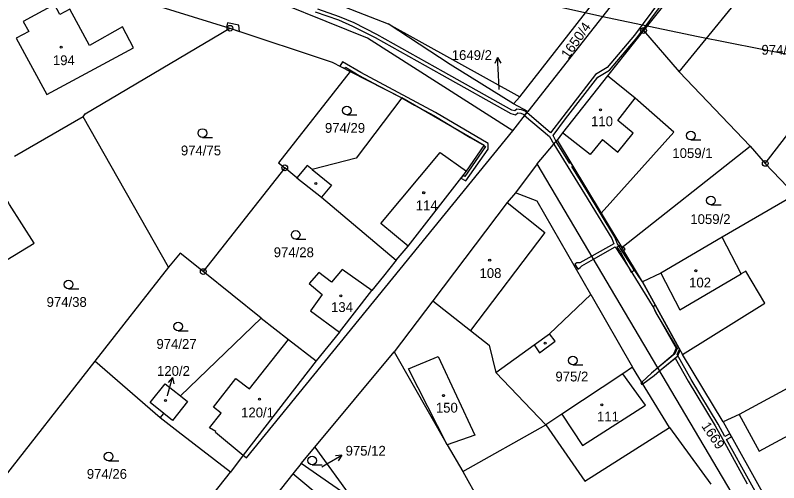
# Model space of a CAD drawing. Extents: x -680203 to -673936, y -1102717 to -1093650.
# Drawn here: x -676795.2 to -676663.1, y -1100739.7 to -1100658.8 of the extents above; entities that cross this region are included whole.
import ezdxf

# ---------------------------------------------------------------- set-up
doc = ezdxf.new("R2010")
doc.units = 0
for name, color, linetype in [('_Ideová část', 7, 'Continuous'), ('SOxx02xx_Koleje_param další_Popis10', 7, 'Continuous'), ('SOxx02xx_Staničení_Popis10', 7, 'Continuous'), ('SOxxxxxx_Koleje_hlavní_body_Popis10', 7, 'Continuous'), ('SOxxxxxx_Koleje_LN_parametry_Popis10', 7, 'Continuous'), ('SOxxxxxx_Koleje_param další_Popis10', 7, 'Continuous'), ('SOxxxxxx_Osa_bod_P', 7, 'Continuous'), ('SOxxxxxx_Staničení_Popis10', 7, 'Continuous'), ('x_prac', 7, 'Continuous')]:
    doc.layers.add(name, color=color, linetype=linetype)

msp = doc.modelspace()

# ---------------------------------------------------------------- linework, layer by layer
at = {"layer": '_Ideová část'}
msp.add_circle((-676417.7, -1099401.52), 1287.12, dxfattribs=at)
at = {"layer": 'SOxx02xx_Koleje_param další_Popis10'}
for centre, radius in [((-676758.11, -1100661.01), 0.5), ((-676758.11, -1100661.01), 0.0303), ((-676686.55, -1100661.4), 0.5), ((-676686.55, -1100661.4), 0.0303), ((-676665.48, -1100684.42), 0.5), ((-676665.48, -1100684.42), 0.0303), ((-676748.62, -1100685.19), 0.5), ((-676748.62, -1100685.19), 0.0303), ((-676762.71, -1100703.16), 0.5), ((-676762.71, -1100703.16), 0.0303)]:
    msp.add_circle(centre, radius, dxfattribs=at)
at = {"layer": 'SOxx02xx_Staničení_Popis10'}
for p, q in [((-676711.8, -1100666.08), (-676712.24, -1100667.11)), ((-676711.64, -1100669.08), (-676711.8, -1100666.08)), ((-676711.8, -1100666.08), (-676711.24, -1100667.06)), ((-676711.51, -1100671.62), (-676711.64, -1100669.08)), ((-676768.84, -1100724.41), (-676768.06, -1100721.51)), ((-676768.06, -1100721.51), (-676768.81, -1100722.35)), ((-676768.06, -1100721.51), (-676767.84, -1100722.61)), ((-676768.91, -1100724.66), (-676768.84, -1100724.41)), ((-676741.34, -1100736.48), (-676738.74, -1100734.98)), ((-676738.74, -1100734.98), (-676739.86, -1100735.05)), ((-676738.74, -1100734.98), (-676739.36, -1100735.91)), ((-676742.18, -1100736.97), (-676741.34, -1100736.48))]:
    msp.add_line(p, q, dxfattribs=at)
at = {"layer": 'SOxxxxxx_Koleje_hlavní_body_Popis10'}
for p, q in [((-676737.89, -1100676), (-676736.14, -1100676)), ((-676762.87, -1100679.91), (-676761.12, -1100679.91)), ((-676678.35, -1100680.36), (-676676.6, -1100680.36)), ((-676674.87, -1100691.58), (-676673.12, -1100691.58)), ((-676746.73, -1100697.53), (-676744.98, -1100697.53)), ((-676786.02, -1100706.14), (-676784.27, -1100706.14)), ((-676767.08, -1100713.42), (-676765.33, -1100713.42)), ((-676698.77, -1100719.32), (-676697.02, -1100719.32)), ((-676779.09, -1100735.93), (-676777.34, -1100735.93)), ((-676743.87, -1100736.61), (-676742.12, -1100736.61))]:
    msp.add_line(p, q, dxfattribs=at)
for centre in [(-676737.89, -1100675.25), (-676762.87, -1100679.16), (-676678.35, -1100679.61), (-676674.87, -1100690.83), (-676746.73, -1100696.78), (-676786.02, -1100705.39), (-676767.08, -1100712.67), (-676698.77, -1100718.57), (-676779.09, -1100735.18), (-676743.87, -1100735.86)]:
    msp.add_circle(centre, 0.75, dxfattribs=at)
at = {"layer": 'SOxxxxxx_Koleje_LN_parametry_Popis10'}
for points in [[(-676662.09, -1100628.29), (-676666.67, -1100634.24), (-676670.09, -1100639.09), (-676677.03, -1100647.89), (-676683.58, -1100656.15), (-676688.08, -1100662.21), (-676692.84, -1100667.81), (-676694.86, -1100669), (-676700.53, -1100676.36), (-676702.61, -1100679.14), (-676706.75, -1100675.62), (-676707.12, -1100676.1), (-676702.8, -1100679.76), (-676702.06, -1100681.09), (-676696.73, -1100689.68), (-676692.05, -1100697.44), (-676691.7, -1100698.34), (-676695.5, -1100700.49), (-676697.54, -1100701.64)], [(-676666.3, -1100742.87), (-676668.09, -1100739.65), (-676672.16, -1100732.23), (-676671.3, -1100731.77), (-676671.6, -1100731.25), (-676672.45, -1100731.7), (-676673.63, -1100729.59), (-676678.3, -1100721.84), (-676680.73, -1100717.54), (-676680.3, -1100716.59), (-676686.73, -1100704.91), (-676688.65, -1100702.05), (-676691.06, -1100698.33), (-676691.51, -1100697.18), (-676696.21, -1100689.36), (-676698.96, -1100684.96), (-676698.74, -1100684.95), (-676699.2, -1100684.18), (-676699.27, -1100684.45), (-676701.65, -1100680.6), (-676702.2, -1100679.59), (-676700.05, -1100676.72), (-676694.46, -1100669.46), (-676692.44, -1100668.27), (-676687.62, -1100662.59), (-676683.1, -1100656.51)], [(-676743.35, -1100658.15), (-676739.34, -1100659.57), (-676736.87, -1100660.62), (-676732.96, -1100662.63), (-676721.44, -1100669.07), (-676709.52, -1100675.77), (-676708.67, -1100675.99), (-676708.27, -1100675.64), (-676707.79, -1100675.7), (-676707.34, -1100675.91), (-676707.12, -1100676.1), (-676706.75, -1100675.62), (-676707.02, -1100675.39), (-676707.63, -1100675.12), (-676708.47, -1100675.02), (-676708.83, -1100675.33), (-676709.3, -1100675.21), (-676721.14, -1100668.55), (-676732.68, -1100662.11), (-676736.61, -1100660.08), (-676739.12, -1100659.01), (-676742.9, -1100657.68)], [(-676697.54, -1100701.64), (-676698.05, -1100701.62), (-676698.43, -1100701.86), (-676697.89, -1100702.71), (-676697.51, -1100702.47), (-676697.24, -1100702.16), (-676695.2, -1100701), (-676691.43, -1100698.87), (-676689.15, -1100702.37), (-676684.75, -1100709.52), (-676684.43, -1100710.27), (-676680.89, -1100716.44), (-676681.4, -1100717.57), (-676684.07, -1100719.83), (-676685.13, -1100720.73), (-676686.85, -1100722.3), (-676686.66, -1100722.6), (-676684.69, -1100721.13), (-676683.75, -1100720.36), (-676681.07, -1100718.14), (-676678.82, -1100722.14), (-676674.16, -1100729.88), (-676672.83, -1100732.25), (-676668.62, -1100739.94)]]:
    msp.add_lwpolyline(points, dxfattribs=at)
for points in [[(-676758.7, -1100660.83), (-676758.11, -1100661.01), (-676756.44, -1100661.57), (-676756.55, -1100660.45), (-676758.55, -1100660.07)], [(-676739.06, -1100667.58), (-676738.25, -1100667.99), (-676738.11, -1100667.77), (-676735.77, -1100669.19), (-676732.42, -1100670.99), (-676728.34, -1100673.08), (-676726.17, -1100674.34), (-676722.82, -1100676.13), (-676716.53, -1100679.91), (-676714.14, -1100681.29), (-676714.17, -1100681.33), (-676713.88, -1100681.5), (-676717.48, -1100686.67), (-676717.76, -1100686.53), (-676718.13, -1100687), (-676717.28, -1100687.43), (-676713.4, -1100681.97), (-676713.41, -1100681), (-676722.52, -1100675.61), (-676735.47, -1100668.67), (-676738.64, -1100666.81)], [(-676691.13, -1100698.92), (-676690.5, -1100699.81), (-676688.68, -1100703.24), (-676688.16, -1100702.94), (-676689.99, -1100699.5), (-676690.3, -1100698.98), (-676690.61, -1100698.62)], [(-676690.3, -1100698.98), (-676689.99, -1100699.5), (-676689.73, -1100699.3), (-676690.08, -1100698.81)], [(-676684.06, -1100719.84), (-676683.75, -1100720.36), (-676680.62, -1100717.76), (-676680.2, -1100716.78), (-676684.48, -1100709), (-676684.85, -1100709.28), (-676684.43, -1100710.28), (-676680.74, -1100716.5), (-676681.12, -1100717.4)], [(-676686.86, -1100722.7), (-676686.66, -1100722.6), (-676686.85, -1100722.3), (-676686.99, -1100722.43)]]:
    msp.add_lwpolyline(points, close=True, dxfattribs=at)
at = {"layer": 'SOxxxxxx_Koleje_param další_Popis10'}
for centre in [(-676787.3, -1100664.27), (-676694, -1100675.13), (-676743.23, -1100687.9), (-676724.58, -1100689.49), (-676713.16, -1100701.18), (-676677.47, -1100703), (-676738.9, -1100707.37), (-676703.55, -1100715.56), (-676769.27, -1100725.49), (-676752.99, -1100725.27), (-676721.17, -1100724.64), (-676693.74, -1100726.24)]:
    msp.add_circle(centre, 0.175, dxfattribs=at)
at = {"layer": 'SOxxxxxx_Staničení_Popis10'}
for p, q in [((-676691.01, -1100676.98), (-676687.97, -1100673.1)), ((-676688.31, -1100679.21), (-676691.01, -1100676.98)), ((-676695.76, -1100682.9), (-676700.54, -1100679.12)), ((-676693.65, -1100680.28), (-676695.76, -1100682.9)), ((-676693.65, -1100680.28), (-676690.99, -1100682.47)), ((-676690.99, -1100682.47), (-676688.31, -1100679.21)), ((-676731.99, -1100694.83), (-676721.71, -1100682.53)), ((-676721.71, -1100682.53), (-676717.15, -1100685.74)), ((-676743.85, -1100685.45), (-676740.51, -1100688.18)), ((-676740.51, -1100688.18), (-676742.28, -1100690.29)), ((-676710.14, -1100691.21), (-676703.64, -1100696.37)), ((-676727.29, -1100698.77), (-676731.99, -1100694.83)), ((-676703.64, -1100696.37), (-676716.47, -1100713.35)), ((-676683.54, -1100703.43), (-676680.23, -1100709.78)), ((-676680.23, -1100709.78), (-676669.67, -1100703.56)), ((-676705.49, -1100715.87), (-676702.79, -1100713.91)), ((-676754.7, -1100723.45), (-676747.99, -1100714.94)), ((-676727.19, -1100719.99), (-676722.08, -1100717.87)), ((-676722.08, -1100717.87), (-676715.73, -1100731.48)), ((-676720.53, -1100733.15), (-676727.19, -1100719.99)), ((-676686.19, -1100726.27), (-676690.1, -1100720.87)), ((-676760.94, -1100726.64), (-676757.08, -1100721.67)), ((-676757.08, -1100721.67), (-676754.7, -1100723.45)), ((-676759.64, -1100727.66), (-676760.94, -1100726.64)), ((-676697.08, -1100733.27), (-676686.19, -1100726.27)), ((-676666.5, -1100734.25), (-676652.22, -1100726.48)), ((-676761.65, -1100730.23), (-676759.64, -1100727.66)), ((-676700.7, -1100727.88), (-676697.08, -1100733.27)), ((-676669.97, -1100727.91), (-676666.5, -1100734.25)), ((-676760.55, -1100730.88), (-676761.65, -1100730.23)), ((-676760.62, -1100730.97), (-676760.55, -1100730.88)), ((-676760.62, -1100730.97), (-676755.81, -1100734.93)), ((-676715.73, -1100731.48), (-676720.53, -1100733.15)), ((-676741.08, -1100743.29), (-676747.24, -1100738.19))]:
    msp.add_line(p, q, dxfattribs=at)
at = {"layer": 'x_prac'}
for p, q in [((-676748.29, -1100653.33), (-676730.75, -1100660.26)), ((-676707.95, -1100672.9), (-676692.56, -1100653.2)), ((-676689.92, -1100654.2), (-676706.58, -1100675.41)), ((-676730.75, -1100660.26), (-676707.95, -1100672.9)), ((-676686.55, -1100661.4), (-676692.79, -1100669.24)), ((-676686.55, -1100661.4), (-676680.37, -1100668.55)), ((-676737.3, -1100668.48), (-676728.34, -1100673.08)), ((-676680.37, -1100668.55), (-676668.06, -1100681.45)), ((-676665.48, -1100684.42), (-676654.34, -1100669.87)), ((-676709.04, -1100674.09), (-676707.95, -1100672.9)), ((-676706.58, -1100675.41), (-676709.04, -1100674.09)), ((-676783.48, -1100676.34), (-676795.41, -1100683.25)), ((-676768.72, -1100702.4), (-676783.48, -1100676.34)), ((-676709.18, -1100678.75), (-676706.58, -1100675.41)), ((-676704.94, -1100684.52), (-676701.48, -1100680.4)), ((-676701.48, -1100680.4), (-676693.86, -1100693.06)), ((-676690.3, -1100698.98), (-676668.06, -1100681.45)), ((-676668.06, -1100681.45), (-676665.48, -1100684.42)), ((-676748.62, -1100685.19), (-676762.71, -1100703.16)), ((-676746.55, -1100686.89), (-676748.62, -1100685.19)), ((-676704.94, -1100684.52), (-676708.68, -1100689.51)), ((-676645.24, -1100785.51), (-676704.94, -1100684.52)), ((-676665.48, -1100684.42), (-676660.31, -1100689.84)), ((-676660.31, -1100689.84), (-676672.92, -1100697.22)), ((-676693.86, -1100693.06), (-676690.3, -1100698.98)), ((-676686.73, -1100704.91), (-676690.3, -1100698.98)), ((-676768.72, -1100702.4), (-676781.48, -1100718.65)), ((-676752.68, -1100711.23), (-676762.71, -1100703.16)), ((-676686.73, -1100704.91), (-676679.78, -1100717.54)), ((-676739.12, -1100713.65), (-676733.54, -1100706.46)), ((-676695.66, -1100707.12), (-676688.43, -1100719.71)), ((-676722.97, -1100708.23), (-676729.69, -1100717.04)), ((-676766.64, -1100724.7), (-676752.68, -1100711.23)), ((-676739.12, -1100713.65), (-676743.17, -1100718.64)), ((-676743.39, -1100733.54), (-676729.69, -1100717.04)), ((-676781.48, -1100718.65), (-676798.35, -1100740.16)), ((-676770.19, -1100728.46), (-676781.48, -1100718.65)), ((-676743.17, -1100718.64), (-676755.81, -1100734.93)), ((-676672.75, -1100729.17), (-676679.78, -1100717.54)), ((-676682.05, -1100730.15), (-676688.43, -1100719.71)), ((-676703.47, -1100729.69), (-676712.12, -1100720.62)), ((-676771.89, -1100725.84), (-676769.3, -1100722.57)), ((-676769.3, -1100722.57), (-676766.64, -1100724.7)), ((-676766.64, -1100724.7), (-676765.43, -1100725.67)), ((-676769.53, -1100727.73), (-676771.89, -1100725.84)), ((-676765.43, -1100725.67), (-676768.03, -1100728.93)), ((-676770.19, -1100728.46), (-676769.53, -1100727.73)), ((-676768.03, -1100728.93), (-676769.53, -1100727.73)), ((-676672.75, -1100729.17), (-676664.39, -1100744.2)), ((-676717.81, -1100737.78), (-676703.47, -1100729.69)), ((-676682.05, -1100730.15), (-676674.9, -1100740)), ((-676745.79, -1100736.42), (-676743.39, -1100733.54)), ((-676743.39, -1100733.54), (-676736.92, -1100742.59)), ((-676755.81, -1100734.93), (-676758.01, -1100737.87)), ((-676736.92, -1100742.59), (-676745.79, -1100736.42)), ((-676764.75, -1100746.35), (-676758.01, -1100737.87)), ((-676717.81, -1100737.78), (-676708.66, -1100754.11))]:
    msp.add_line(p, q, dxfattribs=at)
for points in [[(-676669.67, -1100639.85), (-676673.67, -1100645.24), (-676686.55, -1100661.4)], [(-676709.18, -1100678.75), (-676734.3, -1100662.71), (-676756.05, -1100653.9), (-676763.65, -1100652.93), (-676793.56, -1100645.53), (-676846.54, -1100654.45)], [(-676680.37, -1100668.55), (-676666.13, -1100651.07), (-676662.17, -1100646.2)], [(-676811.35, -1100650.91), (-676804.57, -1100650.11), (-676787.4, -1100651.88), (-676758.11, -1100661.01)], [(-676795.09, -1100662.75), (-676789.79, -1100672.48), (-676774.8, -1100664.38), (-676776.71, -1100660.76), (-676782.39, -1100664), (-676785.82, -1100657.73), (-676787.51, -1100658.64), (-676788.45, -1100656.91), (-676793.87, -1100659.85), (-676792.93, -1100661.58), (-676795.09, -1100662.75)], [(-676709.04, -1100674.09), (-676720.02, -1100667.27), (-676730.75, -1100660.26)], [(-676783.48, -1100676.34), (-676783.18, -1100675.81), (-676758.11, -1100661.01)], [(-676758.11, -1100661.01), (-676740.43, -1100666.88), (-676737.3, -1100668.48)], [(-676737.3, -1100668.48), (-676749.69, -1100684.3), (-676748.62, -1100685.19)], [(-676692.79, -1100669.24), (-676700.54, -1100679.12), (-676701.48, -1100680.4)], [(-676693.86, -1100693.06), (-676681.31, -1100679.01), (-676687.97, -1100673.1), (-676692.79, -1100669.24)], [(-676728.34, -1100673.08), (-676736.24, -1100683.54), (-676743.85, -1100685.45), (-676744.74, -1100684.79), (-676746.55, -1100686.89)], [(-676729.36, -1100701.18), (-676727.29, -1100698.77), (-676717.15, -1100685.74), (-676714.14, -1100681.29), (-676728.34, -1100673.08)], [(-676755.81, -1100734.93), (-676755.21, -1100735.39), (-676709.18, -1100678.75)], [(-676810.29, -1100719.97), (-676807.26, -1100717.96), (-676799.08, -1100713.09), (-676801.48, -1100709.59), (-676798.95, -1100707.94), (-676801.5, -1100704.03), (-676792, -1100698.22), (-676796.22, -1100691.55), (-676799.06, -1100686.57), (-676799.73, -1100685.51)], [(-676746.55, -1100686.89), (-676742.28, -1100690.29), (-676729.36, -1100701.18)], [(-676708.68, -1100689.51), (-676710.14, -1100691.21), (-676722.97, -1100708.23)], [(-676695.66, -1100707.12), (-676704.94, -1100690.94), (-676708.68, -1100689.51)], [(-676672.92, -1100697.22), (-676683.54, -1100703.43), (-676686.73, -1100704.91)], [(-676679.78, -1100717.54), (-676665.54, -1100708.62), (-676668.84, -1100703.09), (-676669.67, -1100703.56), (-676672.92, -1100697.22)], [(-676762.71, -1100703.16), (-676766.71, -1100699.95), (-676768.72, -1100702.4)], [(-676729.36, -1100701.18), (-676731.53, -1100703.95), (-676733.54, -1100706.46)], [(-676733.54, -1100706.46), (-676738.67, -1100702.8), (-676740.51, -1100704.98), (-676742.74, -1100703.31), (-676744.37, -1100705.24), (-676742.14, -1100707.12), (-676744.16, -1100709.93), (-676739.12, -1100713.65)], [(-676712.12, -1100720.62), (-676705.49, -1100715.87), (-676704.51, -1100717.21), (-676701.82, -1100715.22), (-676702.79, -1100713.91), (-676695.66, -1100707.12)], [(-676722.97, -1100708.23), (-676716.47, -1100713.35), (-676713.22, -1100715.91), (-676712.12, -1100720.62)], [(-676752.68, -1100711.23), (-676747.99, -1100714.94), (-676743.17, -1100718.64)], [(-676729.69, -1100717.04), (-676720.53, -1100733.15), (-676717.81, -1100737.78)], [(-676688.43, -1100719.71), (-676690.1, -1100720.87), (-676700.7, -1100727.88), (-676703.47, -1100729.69)], [(-676655.94, -1100720.27), (-676669.97, -1100727.91), (-676672.75, -1100729.17)], [(-676758.01, -1100737.87), (-676767.09, -1100730.93), (-676770.19, -1100728.46)], [(-676703.47, -1100729.69), (-676696.71, -1100739.46), (-676682.05, -1100730.15)], [(-676745.79, -1100736.42), (-676747.24, -1100738.19), (-676756.77, -1100750.3)]]:
    msp.add_lwpolyline(points, dxfattribs=at)

# ---------------------------------------------------------------- texts
at = {"layer": 'SOxxxxxx_Osa_bod_P'}
for s, rotation, p in [('1650/4', 55, (-676699.55, -1100666.44)), ('1669', 304, (-676676.6, -1100729.91))]:
    msp.add_text(s, height=1.7, rotation=rotation, dxfattribs=at).set_placement(p)
for s, p in [('974/42', (-676666.13, -1100665.59)), ('194', (-676788.74, -1100667.4)), ('1649/2', (-676719.72, -1100666.51)), ('110', (-676695.62, -1100677.98)), ('974/29', (-676741.67, -1100679.12)), ('974/75', (-676766.59, -1100683.03)), ('1059/1', (-676681.55, -1100683.49)), ('114', (-676725.94, -1100692.54)), ('1059/2', (-676678.44, -1100694.92)), ('974/28', (-676750.53, -1100700.66)), ('108', (-676714.92, -1100704.27)), ('102', (-676678.65, -1100705.9)), ('974/38', (-676789.83, -1100709.27)), ('134', (-676740.61, -1100710.16)), ('974/27', (-676770.82, -1100716.54)), ('120/2', (-676770.72, -1100721.22)), ('975/2', (-676701.78, -1100722.18)), ('120/1', (-676756.17, -1100728.41)), ('150', (-676722.47, -1100727.58)), ('111', (-676694.59, -1100729.12)), ('975/12', (-676738.09, -1100735.04)), ('974/26', (-676782.87, -1100739.05))]:
    msp.add_text(s, height=1.7, dxfattribs=at).set_placement(p)

doc.saveas('drawing.dxf')
